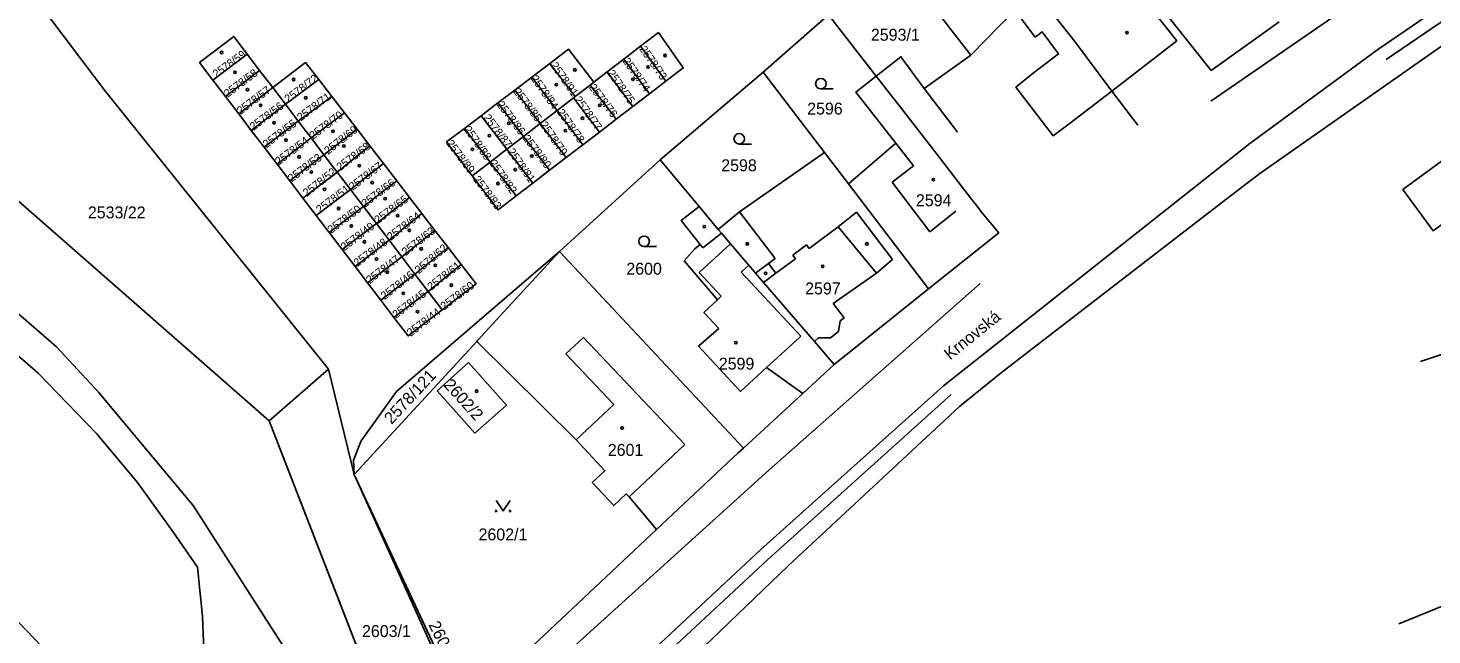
# Model space of a CAD drawing. Extents: x -527335 to -526256, y -1079142 to -1077836.
# Drawn here: x -526804.5 to -526604.5, y -1078442 to -1078355.5 of the extents above; entities that cross this region are included whole.
import ezdxf

# ---------------------------------------------------------------- set-up
doc = ezdxf.new("R2010")
doc.units = 0
for name, color, linetype in [('Hranice parcel', 7, 'Continuous'), ('Parcelní čísla', 7, 'Continuous'), ('Pop  PČ popisy', 7, 'Continuous'), ('Vnitřní kresba', 7, 'Continuous'), ('Vrstva 54', 7, 'Continuous'), ('Značky budov', 7, 'Continuous'), ('Značky kultur', 7, 'Continuous')]:
    doc.layers.add(name, color=color, linetype=linetype)

msp = doc.modelspace()

# ---------------------------------------------------------------- linework, layer by layer
at = {"layer": 'Hranice parcel'}
for p, q in [((-526652.31, -1078340.92), (-526635.98, -1078361.55)), ((-526681.04, -1078345.37), (-526670.21, -1078359.37)), ((-526699.79, -1078361.79), (-526690.48, -1078353.62)), ((-526690.48, -1078353.62), (-526683.67, -1078362.36)), ((-526635.98, -1078361.55), (-526626.29, -1078354.62)), ((-526719.62, -1078359.93), (-526717.25, -1078358.1)), ((-526717.25, -1078358.1), (-526713.66, -1078363.1)), ((-526773.29, -1078359.21), (-526778.15, -1078362.93)), ((-526773.29, -1078359.21), (-526771.51, -1078361.55)), ((-526732.74, -1078362.52), (-526730.16, -1078360.55)), ((-526726.55, -1078365.27), (-526730.16, -1078360.55)), ((-526722, -1078361.76), (-526719.62, -1078359.93)), ((-526719.62, -1078359.93), (-526715.97, -1078364.88)), ((-526776.36, -1078365.27), (-526778.15, -1078362.93)), ((-526771.51, -1078361.55), (-526776.36, -1078365.27)), ((-526771.51, -1078361.55), (-526769.64, -1078363.99)), ((-526763.09, -1078362.84), (-526767.83, -1078366.37)), ((-526763.09, -1078362.84), (-526761.21, -1078365.28)), ((-526735.17, -1078364.36), (-526732.74, -1078362.52)), ((-526732.74, -1078362.52), (-526729.13, -1078367.26)), ((-526723.9, -1078363.23), (-526722, -1078361.76)), ((-526722, -1078361.76), (-526718.33, -1078366.69)), ((-526714.46, -1078374.28), (-526699.79, -1078361.79)), ((-526699.79, -1078361.79), (-526691.04, -1078373.25)), ((-526769.64, -1078363.99), (-526774.49, -1078367.74)), ((-526767.83, -1078366.37), (-526769.64, -1078363.99)), ((-526737.56, -1078366.18), (-526735.17, -1078364.36)), ((-526735.17, -1078364.36), (-526731.54, -1078369.12)), ((-526724.41, -1078363.63), (-526726.55, -1078365.27)), ((-526723.9, -1078363.23), (-526724.41, -1078363.63)), ((-526724.41, -1078363.63), (-526720.71, -1078368.51)), ((-526715.97, -1078364.88), (-526718.33, -1078366.69)), ((-526713.66, -1078363.1), (-526715.97, -1078364.88)), ((-526774.49, -1078367.74), (-526776.36, -1078365.27)), ((-526767.83, -1078366.37), (-526772.69, -1078370.09)), ((-526766.01, -1078368.77), (-526767.83, -1078366.37)), ((-526761.21, -1078365.28), (-526766.01, -1078368.77)), ((-526761.21, -1078365.28), (-526759.44, -1078367.57)), ((-526739.94, -1078368), (-526737.56, -1078366.18)), ((-526737.56, -1078366.18), (-526733.92, -1078370.95)), ((-526726.79, -1078365.46), (-526729.13, -1078367.26)), ((-526726.55, -1078365.27), (-526726.79, -1078365.46)), ((-526726.79, -1078365.46), (-526723.09, -1078370.33)), ((-526718.33, -1078366.69), (-526720.71, -1078368.51)), ((-526772.69, -1078370.09), (-526774.49, -1078367.74)), ((-526766.01, -1078368.77), (-526770.86, -1078372.49)), ((-526764.18, -1078371.17), (-526766.01, -1078368.77)), ((-526759.44, -1078367.57), (-526764.18, -1078371.17)), ((-526759.44, -1078367.57), (-526757.63, -1078369.93)), ((-526742.33, -1078369.81), (-526739.94, -1078368)), ((-526739.94, -1078368), (-526736.3, -1078372.78)), ((-526729.13, -1078367.26), (-526731.54, -1078369.12)), ((-526729.13, -1078367.26), (-526725.47, -1078372.15)), ((-526720.71, -1078368.51), (-526723.09, -1078370.33)), ((-526770.86, -1078372.49), (-526772.69, -1078370.09)), ((-526757.63, -1078369.93), (-526762.36, -1078373.56)), ((-526757.63, -1078369.93), (-526755.79, -1078372.32)), ((-526742.33, -1078369.81), (-526738.67, -1078374.61)), ((-526733.92, -1078370.95), (-526736.3, -1078372.78)), ((-526731.54, -1078369.12), (-526733.92, -1078370.95)), ((-526733.92, -1078370.95), (-526730.23, -1078375.79)), ((-526731.54, -1078369.12), (-526727.85, -1078373.97)), ((-526723.09, -1078370.33), (-526725.47, -1078372.15)), ((-526769.03, -1078374.89), (-526770.86, -1078372.49)), ((-526764.18, -1078371.17), (-526769.03, -1078374.89)), ((-526762.36, -1078373.56), (-526764.18, -1078371.17)), ((-526755.79, -1078372.32), (-526760.48, -1078376.03)), ((-526755.79, -1078372.32), (-526753.87, -1078374.82)), ((-526736.3, -1078372.78), (-526738.67, -1078374.61)), ((-526736.3, -1078372.78), (-526732.61, -1078377.62)), ((-526725.47, -1078372.15), (-526727.85, -1078373.97)), ((-526767.21, -1078377.28), (-526769.03, -1078374.89)), ((-526762.36, -1078373.56), (-526767.21, -1078377.28)), ((-526760.48, -1078376.03), (-526762.36, -1078373.56)), ((-526753.87, -1078374.82), (-526758.57, -1078378.53)), ((-526753.87, -1078374.82), (-526751.97, -1078377.29)), ((-526738.67, -1078374.61), (-526741.21, -1078376.56)), ((-526738.67, -1078374.61), (-526734.98, -1078379.44)), ((-526727.85, -1078373.97), (-526730.23, -1078375.79)), ((-526728.78, -1078387.36), (-526714.46, -1078374.28)), ((-526714.46, -1078374.28), (-526708.91, -1078380.95)), ((-526691.04, -1078373.25), (-526687.64, -1078377.71)), ((-526760.48, -1078376.03), (-526765.34, -1078379.75)), ((-526758.57, -1078378.53), (-526760.48, -1078376.03)), ((-526730.23, -1078375.79), (-526732.61, -1078377.62)), ((-526765.34, -1078379.75), (-526767.21, -1078377.28)), ((-526758.57, -1078378.53), (-526763.43, -1078382.25)), ((-526756.73, -1078380.96), (-526758.57, -1078378.53)), ((-526751.97, -1078377.29), (-526756.73, -1078380.96)), ((-526751.97, -1078377.29), (-526750.15, -1078379.65)), ((-526732.61, -1078377.62), (-526734.98, -1078379.44)), ((-526687.64, -1078377.71), (-526676.21, -1078392.67)), ((-526763.43, -1078382.25), (-526765.34, -1078379.75)), ((-526756.73, -1078380.96), (-526761.58, -1078384.67)), ((-526754.88, -1078383.38), (-526756.73, -1078380.96)), ((-526750.15, -1078379.65), (-526754.88, -1078383.38)), ((-526750.15, -1078379.65), (-526748.39, -1078381.94)), ((-526708.91, -1078380.95), (-526706.18, -1078384.23)), ((-526761.58, -1078384.67), (-526763.43, -1078382.25)), ((-526748.39, -1078381.94), (-526753.06, -1078385.77)), ((-526748.39, -1078381.94), (-526746.53, -1078384.36)), ((-526759.73, -1078387.1), (-526761.58, -1078384.67)), ((-526754.88, -1078383.38), (-526759.73, -1078387.1)), ((-526753.06, -1078385.77), (-526754.88, -1078383.38)), ((-526746.53, -1078384.36), (-526751.27, -1078388.11)), ((-526746.53, -1078384.36), (-526744.66, -1078386.78)), ((-526676.21, -1078392.67), (-526666.21, -1078384.72)), ((-526753.06, -1078385.77), (-526757.91, -1078389.49)), ((-526751.27, -1078388.11), (-526753.06, -1078385.77)), ((-526744.66, -1078386.78), (-526749.4, -1078390.58)), ((-526744.66, -1078386.78), (-526742.78, -1078389.23)), ((-526757.91, -1078389.49), (-526759.73, -1078387.1)), ((-526751.27, -1078388.11), (-526756.13, -1078391.83)), ((-526749.4, -1078390.58), (-526751.27, -1078388.11)), ((-526728.78, -1078387.36), (-526702.59, -1078415.38)), ((-526756.13, -1078391.83), (-526757.91, -1078389.49)), ((-526749.4, -1078390.58), (-526754.25, -1078394.3)), ((-526747.52, -1078393.05), (-526749.4, -1078390.58)), ((-526742.78, -1078389.23), (-526747.52, -1078393.05)), ((-526754.25, -1078394.3), (-526756.13, -1078391.83)), ((-526747.52, -1078393.05), (-526752.37, -1078396.77)), ((-526745.52, -1078395.67), (-526747.52, -1078393.05)), ((-526689.66, -1078403.49), (-526676.21, -1078392.67)), ((-526752.37, -1078396.77), (-526754.25, -1078394.3)), ((-526740.57, -1078400.18), (-526758.04, -1078419.17)), ((-526770.17, -1078411.49), (-526761.68, -1078404.12)), ((-526761.68, -1078404.12), (-526758.04, -1078419.17)), ((-526694.13, -1078407.6), (-526689.66, -1078403.49)), ((-526702.59, -1078415.38), (-526694.13, -1078407.6)), ((-526749.3, -1078465.23), (-526770.17, -1078411.49)), ((-526742.65, -1078453.3), (-526758.04, -1078419.17)), ((-526758.04, -1078419.17), (-526742.34, -1078452.74)), ((-526714.96, -1078427.01), (-526742.34, -1078452.74))]:
    msp.add_line(p, q, dxfattribs=at)
for points in [[(-526538.39, -1078327.72), (-526540.03, -1078327.15), (-526546.04, -1078326.1), (-526550.79, -1078326.44), (-526558.7, -1078329.17), (-526588.71, -1078343.39), (-526596.49, -1078347.76), (-526612.22, -1078358.58), (-526630.45, -1078371.95), (-526674.07, -1078406.52), (-526700.09, -1078429.86), (-526748.62, -1078475.19)], [(-526761.68, -1078404.12), (-526793.59, -1078364.38), (-526804.2, -1078350.27)], [(-526660.83, -1078350.48), (-526664.04, -1078352.82), (-526663.93, -1078352.97), (-526670.21, -1078359.37)], [(-526646.41, -1078369.36), (-526650.13, -1078364.49), (-526655.4, -1078357.43), (-526656.98, -1078355.37), (-526660.83, -1078350.48)], [(-526634.47, -1078380.43), (-526629.02, -1078376.22), (-526594.89, -1078352.31), (-526594.34, -1078352)], [(-526758.4, -1078472.62), (-526766.27, -1078446.58), (-526780.95, -1078423.56), (-526794.44, -1078407.43), (-526800.43, -1078400.96), (-526814.56, -1078388.75), (-526829.06, -1078378.91), (-526860.51, -1078363.6), (-526886.41, -1078357.78), (-526924.51, -1078355.89), (-526949.93, -1078359.99), (-526973.92, -1078367.12), (-526999.06, -1078381.03), (-527019.7, -1078396.51), (-527044.07, -1078424.46), (-527066.65, -1078463.1), (-527068.91, -1078470.58)], [(-526778.15, -1078362.93), (-526780.06, -1078360.42), (-526775.2, -1078356.7), (-526773.29, -1078359.21)], [(-526717.25, -1078358.1), (-526714.71, -1078356.15), (-526711.16, -1078361.18), (-526713.66, -1078363.1)], [(-526730.16, -1078360.55), (-526727.5, -1078358.52), (-526723.9, -1078363.23)], [(-526769.64, -1078363.99), (-526764.95, -1078360.42), (-526763.09, -1078362.84)], [(-526670.21, -1078359.37), (-526676.87, -1078364.1), (-526680.17, -1078359.6), (-526683.67, -1078362.36)], [(-526683.67, -1078362.36), (-526686.57, -1078364.65), (-526680.89, -1078371.93), (-526687.64, -1078377.71)], [(-526683.67, -1078362.36), (-526681.62, -1078364.99), (-526680.27, -1078366.73), (-526675.48, -1078372.93), (-526670.1, -1078379.88), (-526669.15, -1078381.11), (-526668.66, -1078381.74), (-526666.21, -1078384.72)], [(-526608.68, -1078378.53), (-526604.36, -1078384.41), (-526584.89, -1078370.18), (-526589.28, -1078364.31), (-526608.68, -1078378.53)], [(-526741.21, -1078376.56), (-526744.87, -1078371.74), (-526742.33, -1078369.81)], [(-526691.04, -1078373.25), (-526703.15, -1078381.73), (-526706.18, -1078384.23)], [(-526811.67, -1078375.09), (-526792.46, -1078391.93), (-526770.17, -1078411.49)], [(-526734.98, -1078379.44), (-526737.53, -1078381.41), (-526741.21, -1078376.56)], [(-526743.04, -1078478.19), (-526726.54, -1078460.31), (-526716.69, -1078451.83), (-526696.21, -1078432.2), (-526671.8, -1078409.48), (-526665.85, -1078404.63), (-526634.47, -1078380.43)], [(-526708.91, -1078380.95), (-526711.44, -1078382.92), (-526708.75, -1078386.36), (-526709.53, -1078387), (-526711.03, -1078388.68), (-526706.28, -1078394.24), (-526708.22, -1078396.05), (-526706.1, -1078398.32), (-526708.98, -1078400.87), (-526703, -1078407.31), (-526699.3, -1078403.92), (-526694.13, -1078407.6)], [(-526706.18, -1078384.23), (-526705.72, -1078384.77), (-526704.44, -1078386.26), (-526701.91, -1078389.21), (-526701.84, -1078389.29), (-526700.86, -1078390.43), (-526699.71, -1078391.78), (-526692.49, -1078400.19), (-526689.66, -1078403.49)], [(-526758.04, -1078419.17), (-526758.14, -1078417.1), (-526757.05, -1078414.38), (-526752.01, -1078407.3), (-526728.78, -1078387.36)], [(-526728.78, -1078387.36), (-526737.23, -1078396.55), (-526740.42, -1078400.02), (-526740.57, -1078400.18)], [(-526742.78, -1078389.23), (-526740.68, -1078391.96), (-526745.52, -1078395.67)], [(-526602.61, -1078413.24), (-526572.4, -1078403.26), (-526575.82, -1078392.96), (-526606.16, -1078403.06)], [(-526745.52, -1078395.67), (-526750.37, -1078399.39), (-526752.37, -1078396.77)], [(-526740.57, -1078400.18), (-526726.42, -1078414.21), (-526722.33, -1078418.62), (-526724.12, -1078420.28), (-526721.07, -1078423.59), (-526719.28, -1078421.92), (-526718.89, -1078422.34), (-526714.96, -1078427.01)], [(-526741.75, -1078403.21), (-526736.35, -1078409.25), (-526740.84, -1078413.24), (-526746.21, -1078407.22), (-526741.75, -1078403.21)], [(-526714.96, -1078427.01), (-526703.34, -1078416.08), (-526702.59, -1078415.38)], [(-526595.11, -1078434.71), (-526609.22, -1078440.47)], [(-526838.85, -1078458.45), (-526834.26, -1078463.18), (-526807.84, -1078438.11), (-526795.26, -1078451.29), (-526823.96, -1078478.68), (-526825.34, -1078477.23)]]:
    msp.add_lwpolyline(points, dxfattribs=at)
at = {"layer": 'Vnitřní kresba'}
for p, q in [((-526640.86, -1078357.35), (-526646.28, -1078350.48)), ((-526595.86, -1078349.62), (-526611.05, -1078360)), ((-526661.04, -1078356.81), (-526663.93, -1078352.97)), ((-526635.99, -1078365.95), (-526615, -1078351.38)), ((-526650.13, -1078364.49), (-526640.86, -1078357.35)), ((-526672.09, -1078370.33), (-526676.87, -1078364.1)), ((-526680.89, -1078371.93), (-526678.38, -1078375.15)), ((-526678.38, -1078375.15), (-526681.4, -1078377.46)), ((-526681.4, -1078377.46), (-526676.04, -1078384.57)), ((-526703.15, -1078381.73), (-526698.08, -1078388.36)), ((-526689.09, -1078383.83), (-526686.48, -1078381.75)), ((-526686.48, -1078381.75), (-526681.36, -1078388.48)), ((-526676.04, -1078384.57), (-526672.33, -1078381.62)), ((-526708.39, -1078386.82), (-526705.72, -1078384.77)), ((-526693.24, -1078386.94), (-526689.09, -1078383.83)), ((-526683.66, -1078390.45), (-526689.09, -1078383.83)), ((-526708.88, -1078390.35), (-526704.44, -1078386.26)), ((-526708.75, -1078386.36), (-526708.39, -1078386.82)), ((-526695.56, -1078387.87), (-526693.62, -1078386.42)), ((-526693.62, -1078386.42), (-526693.24, -1078386.94)), ((-526698.08, -1078388.36), (-526699.03, -1078389.07)), ((-526697.96, -1078390.47), (-526695.18, -1078388.39)), ((-526695.18, -1078388.39), (-526695.56, -1078387.87)), ((-526681.36, -1078388.48), (-526683.66, -1078390.45)), ((-526705.74, -1078393.74), (-526708.88, -1078390.35)), ((-526701.84, -1078389.29), (-526702.92, -1078390.29)), ((-526702.92, -1078390.29), (-526694.4, -1078399.43)), ((-526699.03, -1078389.07), (-526700.86, -1078390.43)), ((-526699.71, -1078391.78), (-526697.96, -1078390.47)), ((-526697.96, -1078390.47), (-526699.03, -1078389.07)), ((-526683.66, -1078390.45), (-526689.79, -1078394.8)), ((-526816.66, -1078392.88), (-526803.07, -1078404.72)), ((-526698.99, -1078418.52), (-526668.85, -1078391.92)), ((-526706.28, -1078394.24), (-526705.74, -1078393.74)), ((-526689.79, -1078394.8), (-526688.23, -1078396.8)), ((-526688.23, -1078396.8), (-526688.81, -1078397.27)), ((-526689.03, -1078398.75), (-526690.18, -1078399.66)), ((-526688.81, -1078397.27), (-526689.03, -1078398.75)), ((-526727.91, -1078401.95), (-526725.37, -1078399.61)), ((-526725.37, -1078399.61), (-526710.93, -1078414.89)), ((-526694.62, -1078399.63), (-526699.3, -1078403.92)), ((-526694.4, -1078399.43), (-526694.62, -1078399.63)), ((-526691.91, -1078399.69), (-526692.49, -1078400.19)), ((-526690.18, -1078399.66), (-526691.91, -1078399.69)), ((-526721.03, -1078409.18), (-526727.91, -1078401.95)), ((-526803.07, -1078404.72), (-526794.74, -1078413.32)), ((-526673.02, -1078407.75), (-526699.14, -1078431.3)), ((-526726.42, -1078414.21), (-526721.03, -1078409.18)), ((-526794.74, -1078413.32), (-526788.9, -1078420.29)), ((-526710.93, -1078414.89), (-526714.25, -1078418.03)), ((-526739.69, -1078455.4), (-526698.99, -1078418.52)), ((-526714.25, -1078418.03), (-526718.89, -1078422.34)), ((-526788.9, -1078420.29), (-526783.79, -1078427.44)), ((-526783.79, -1078427.44), (-526780.36, -1078432.37)), ((-526780.36, -1078432.37), (-526779.62, -1078439.41)), ((-526699.14, -1078431.3), (-526719.66, -1078450.36)), ((-526778.46, -1078469.48), (-526779.62, -1078439.41))]:
    msp.add_line(p, q, dxfattribs=at)
msp.add_lwpolyline([(-526650.13, -1078364.49), (-526656.19, -1078369.16), (-526658.45, -1078370.87), (-526663.78, -1078363.94), (-526661.51, -1078362.09), (-526657.71, -1078359.2), (-526660.06, -1078356.04), (-526661.04, -1078356.81)], dxfattribs=at)
at = {"layer": 'Vrstva 54'}
for points in [[(-527073.97, -1078460.17), (-527053.17, -1078420.48), (-527032.18, -1078397.77), (-527014.31, -1078382.24), (-527013.19, -1078381.27), (-527008.42, -1078377.49), (-527001.38, -1078371.92), (-526974.73, -1078357.59), (-526955.89, -1078351.06), (-526922.67, -1078344.37), (-526902.66, -1078344.75), (-526884.52, -1078346.04), (-526843.79, -1078358.29), (-526811.67, -1078375.09), (-526792.46, -1078391.93), (-526770.17, -1078411.49), (-526749.3, -1078465.23)], [(-526766.27, -1078446.58), (-526780.95, -1078423.56), (-526794.44, -1078407.43), (-526800.43, -1078400.96), (-526814.56, -1078388.75), (-526829.06, -1078378.91), (-526829.06, -1078378.91), (-526860.51, -1078363.6), (-526886.41, -1078357.78), (-526924.51, -1078355.89), (-526949.93, -1078359.99), (-526973.92, -1078367.12), (-526999.06, -1078381.03), (-527019.7, -1078396.51), (-527044.07, -1078424.46), (-527066.65, -1078463.1)]]:
    msp.add_lwpolyline(points, dxfattribs=at)
at = {"layer": 'Značky budov'}
for centre in [(-526647.94, -1078356.15), (-526776.93, -1078358.99), (-526716.17, -1078361.05), (-526713.75, -1078359.42), (-526775.02, -1078361.81), (-526766.66, -1078362.84), (-526726.61, -1078361.46), (-526718.34, -1078362.83), (-526773.23, -1078364.29), (-526729.23, -1078363.59), (-526771.37, -1078366.54), (-526764.93, -1078365.45), (-526723.08, -1078366.51), (-526769.46, -1078369.01), (-526736.01, -1078369.09), (-526725.52, -1078368.36), (-526761.05, -1078370.22), (-526738.77, -1078370.86), (-526727.95, -1078370.15), (-526767.76, -1078371.49), (-526759.51, -1078372.32), (-526741.19, -1078372.81), (-526765.87, -1078373.87), (-526757.3, -1078375.14), (-526732.73, -1078373.76), (-526764.14, -1078376.02), (-526735.1, -1078375.7), (-526675.54, -1078377.11), (-526762.27, -1078378.51), (-526755.48, -1078377.53), (-526737.56, -1078377.67), (-526760.26, -1078381.23), (-526753.62, -1078379.84), (-526751.84, -1078382.26), (-526758.44, -1078383.73), (-526750.19, -1078384.36), (-526708.17, -1078383.82), (-526756.58, -1078385.98), (-526748.49, -1078386.98), (-526702.05, -1078386.27), (-526685.01, -1078386.27), (-526754.86, -1078388.45), (-526753.33, -1078390.31), (-526746.48, -1078389.33), (-526699.44, -1078390.49), (-526691.3, -1078389.49), (-526744.2, -1078392.16), (-526751.05, -1078393.33), (-526749.02, -1078395.95), (-526703.67, -1078400.36), (-526740.6, -1078407.28), (-526719.86, -1078412.51)]:
    msp.add_circle(centre, 0.175, dxfattribs=at)
at = {"layer": 'Značky kultur'}
for p, q in [((-526691.56, -1078364.18), (-526689.81, -1078364.18)), ((-526703.19, -1078372.04), (-526701.44, -1078372.04)), ((-526716.74, -1078386.66), (-526714.99, -1078386.66))]:
    msp.add_line(p, q, dxfattribs=at)
msp.add_lwpolyline([(-526737.83, -1078422.86), (-526736.83, -1078424.36), (-526735.83, -1078422.86)], dxfattribs=at)
for centre, radius in [((-526691.56, -1078363.43), 0.75), ((-526703.19, -1078371.29), 0.75), ((-526716.74, -1078385.91), 0.75), ((-526737.83, -1078424.36), 0.1), ((-526735.83, -1078424.36), 0.1)]:
    msp.add_circle(centre, radius, dxfattribs=at)

# ---------------------------------------------------------------- texts
at = {"layer": 'Parcelní čísla'}
for s, p in [('2593/1', (-526684.43, -1078357.31)), ('2596', (-526693.51, -1078367.84)), ('2598', (-526705.75, -1078375.92)), ('2533/22', (-526795.97, -1078382.64)), ('2594', (-526678.02, -1078380.9)), ('2600', (-526719.27, -1078390.67)), ('2597', (-526693.8, -1078393.48)), ('2599', (-526706.1, -1078404.2)), ('2601', (-526721.91, -1078416.5)), ('2602/1', (-526740.32, -1078428.55)), ('2603/1', (-526756.92, -1078442.33))]:
    msp.add_text(s, height=1.7, dxfattribs=at).set_placement(p)
for s, height, rotation, p in [('2578/59', 1.1, 36, (-526777.67, -1078362.61)), ('2578/73', 1.14, 305, (-526717.47, -1078358.51)), ('2578/91', 1.14, 305, (-526730.13, -1078360.84)), ('2578/74', 1.14, 305, (-526719.85, -1078360.21)), ('2578/58', 1.14, 37, (-526776.06, -1078365.45)), ('2578/72', 1.139, 37, (-526767.44, -1078366.22)), ('2578/84', 1.14, 305, (-526732.94, -1078362.7)), ('2578/75', 1.14, 305, (-526722.04, -1078361.95)), ('2578/57', 1.14, 37, (-526774.22, -1078367.9)), ('2578/71', 1.14, 37, (-526765.65, -1078368.84)), ('2578/85', 1.14, 307, (-526735.43, -1078364.58)), ('2578/76', 1.14, 307, (-526724.66, -1078363.98)), ('2578/56', 1.14, 37, (-526772.39, -1078370.17)), ('2578/86', 1.14, 307, (-526737.79, -1078366.44)), ('2578/78', 1.14, 305, (-526729.21, -1078367.5)), ('2578/77', 1.14, 305, (-526726.74, -1078365.7)), ('2578/55', 1.14, 37, (-526770.52, -1078372.66)), ('2578/70', 1.14, 37, (-526763.9, -1078371.45)), ('2578/87', 1.139, 307, (-526739.68, -1078368.3)), ('2578/79', 1.14, 305, (-526731.63, -1078369.31)), ('2578/54', 1.14, 37, (-526768.78, -1078375.11)), ('2578/69', 1.139, 38, (-526761.76, -1078373.6)), ('2578/88', 1.14, 305, (-526742.49, -1078369.95)), ('2578/80', 1.14, 307, (-526734.09, -1078371.24)), ('2578/68', 1.139, 37, (-526760.03, -1078375.92)), ('2578/89', 1.14, 307, (-526744.98, -1078371.96)), ('2578/81', 1.14, 305, (-526736.26, -1078373.12)), ('2578/53', 1.14, 37, (-526766.95, -1078377.53)), ('2578/67', 1.14, 37, (-526758.26, -1078378.72)), ('2578/82', 1.14, 305, (-526738.85, -1078374.76)), ('2578/52', 1.139, 38, (-526764.8, -1078379.61)), ('2578/66', 1.14, 37, (-526756.47, -1078381.12)), ('2578/83', 1.139, 307, (-526741.16, -1078377.08)), ('2578/51', 1.139, 37, (-526762.94, -1078381.99)), ('2578/50', 1.14, 37, (-526761.3, -1078384.86)), ('2578/65', 1.14, 37, (-526754.64, -1078383.47)), ('2578/64', 1.14, 37, (-526752.83, -1078385.85)), ('2578/49', 1.14, 37, (-526759.43, -1078387.32)), ('2578/63', 1.139, 38, (-526750.72, -1078388.03)), ('2578/48', 1.14, 37, (-526757.59, -1078389.59)), ('2578/62', 1.139, 40, (-526748.84, -1078390.61)), ('2578/47', 1.14, 37, (-526755.82, -1078392.02)), ('2578/61', 1.139, 38, (-526747.07, -1078392.98)), ('2578/46', 1.139, 38, (-526753.71, -1078394.31)), ('2578/45', 1.14, 37, (-526752.07, -1078396.96)), ('2578/60', 1.14, 37, (-526745.21, -1078395.77)), ('2578/44', 1.14, 37, (-526750.01, -1078399.55)), ('2578/121', 1.7, 47, (-526752.71, -1078412.09)), ('2602/2', 1.7, 312, (-526745.39, -1078406.46)), ('2603/2', 1.7, 296.5516, (-526747.5, -1078440.57))]:
    msp.add_text(s, height=height, rotation=rotation, dxfattribs=at).set_placement(p)
at = {"layer": 'Pop  PČ popisy'}
msp.add_text('Krnovská', height=1.7, rotation=39, dxfattribs=at).set_placement((-526673.16, -1078402.91))

doc.saveas('drawing.dxf')
